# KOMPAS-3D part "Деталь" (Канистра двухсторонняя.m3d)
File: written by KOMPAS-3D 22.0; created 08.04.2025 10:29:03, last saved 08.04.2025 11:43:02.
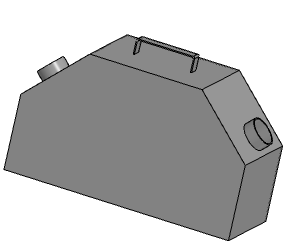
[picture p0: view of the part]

Document properties: Автор: Admin; Полное имя файла: D:\28.11.2016\Абилимпикс\2025\Канистра двухсторонняя.m3d

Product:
- Part/product: Деталь
    Масса: 5.629388

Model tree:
1. Эскиз:2
2. Элемент выдавливания:2
     Расстояние 1 = 2
3. Элемент выдавливания:3  (with: Элемент выдавливания:2)
     Толщина стенки 2 = 2; Расстояние 1 = 166
4. Эскиз:3  (with: Элемент выдавливания:3)
5. Элемент выдавливания:4
     Расстояние 1 = 2
6. Эскиз:4  (with: Элемент выдавливания:2)
7. Элемент выдавливания:5
     Расстояние 1 = 25
8. Эскиз:5  (with: Элемент выдавливания:5)
9. Элемент выдавливания:6
     Расстояние 1 = 2
10. Скругление:1  (with: Элемент выдавливания:6)
     Радиус = 3
11. Эскиз:6  (with: Элемент выдавливания:2)
12. Элемент выдавливания:7  (with: Элемент выдавливания:2)
     Расстояние 1 = 20
13. Эскиз:7  (with: Элемент выдавливания:7)
14. Элемент выдавливания:8
     Расстояние 2 = 50
15. Эскиз:8  (with: Элемент выдавливания:2)
16. Элемент выдавливания:9
     Расстояние 1 = 20
17. Эскиз:9  (with: Элемент выдавливания:9)
18. Элемент выдавливания:10
     Расстояние 2 = 50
